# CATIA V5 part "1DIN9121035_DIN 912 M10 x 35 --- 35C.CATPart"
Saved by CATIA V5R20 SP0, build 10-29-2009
Part number: 1DIN9121035_DIN 912 M10 x 35 --- 35C
Revision: ANY
Definition: UNKNOWN
Nomenclature: 1DIN9121035_DIN 912 M10 x 35 --- 35C
Source: Unknown
Bounding box of the stored display mesh (mm): x 0 to 45, y -8 to 8, z -8 to 8
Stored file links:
  C:\Users\Utente\Desktop\IO LAVORO\3D X SITO CF\CUMSA\3D files SX.256062\SX 256062\1DIN9121035_DIN 912 M10 x 35 --- 35C.CATPart
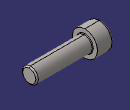
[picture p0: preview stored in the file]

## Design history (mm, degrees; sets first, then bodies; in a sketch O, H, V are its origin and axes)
Body1 "Hex" (main body)
  Solid1: solid without history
